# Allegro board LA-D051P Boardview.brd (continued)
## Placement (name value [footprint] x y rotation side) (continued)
RE353  10K_0402_5%  [R_0402]  142.55 22.71 90 top
RE354  100K_0402_5%  [R_0402]  147.82 21.82 90 top
RE355  10K_0402_5%  [R_0402]  131.63 22.2 90 top
RE356  100K_0402_5%  [R_0402]  154.36 12.55 90 top
RE357  1K_0402_5%  [R_0402]  128.15 13.64 180 top
RE358  100K_0402_5%  [R_0402]  150.16 5.77 0 top
RE359  10K_0402_5%  [R_0402]  123.62 9.26 0 top
RE360  100K_0402_5%  [R_0402]  128.09 8.44 180 top
RE361  100K_0402_5%  [R_0402]  128.15 17.52 180 top
RE362  0_0402_5%  [R0402_0OHM]  123.62 8.37 0 top
RE363  10K_0402_5%  [R_0402]  140.9 24.96 270 top
RE364  43_0402_1%  [R_0402]  126.31 4.5 180 top
RE365  0_0402_5%  [R_0402]  124.53 4.5 180 top
RE366  10_0402_5%  [R_0402]  140.01 24.96 270 top
RE367  0_0402_5%  [R_0402]  124.53 7.29 180 top
RE368  0_0402_5%  [R0402_0OHM]  124.53 5.39 180 top
RE369  1K_0402_5%  [R_0402]  155.81 3.67 0 top
RE370  100K_0402_5%  [R_0402]  148.63 3.74 0 top
RE371  100K_0402_5%  [R_0402]  155.81 2.72 0 top
RE372  15_0402_1%  [R_0402]  151.01 21.9 180 top
RE373  15_0402_1%  [R_0402]  151.01 19.04 180 top
RE374  15_0402_1%  [R_0402]  151.01 19.99 180 top
RE375  0_0402_5%  [R0402_0OHM]  152.39 17.33 0 top
RE376  100K_0402_5%  [R_0402]  153.42 5.71 180 top
RE377  0_0402_5%  [R0402_0OHM]  150.09 18.09 0 top
RE378  10K_0402_5%  [R_0402]  152.51 6.6 0 top
RE379  10K_0402_5%  [R_0402]  154.3 9.06 90 top
RE380  10K_0402_1%  [R_0402]  153.3 16.44 180 top
RE381  0_0402_5%  [R0402_0OHM]  138.23 21.82 90 top
RE382  0_0402_5%  [R0402_0OHM]  142.98 1.58 0 top
RE383  10K_0402_1%  [R_0402]  151 16.23 90 top
RE384  100K_0402_5%  [R_0402]  123.62 10.28 0 top
RE385  0_0603_5%  [R0603_0OHM]  114.55 1.77 90 top
RE386  300_0402_5%  [R_0402]  124.53 2.59 180 top
RE387  100K_0402_5%  [R_0402]  123.62 11.17 0 top
RE388  100K_0402_5%  [R_0402]  124.53 12.06 180 top
RE389  300_0402_5%  [R_0402]  121.48 2.59 180 top
RE390  49.9_0402_1%  [R_0402]  122.24 3.61 180 top
RE391  10K_0402_5%  [R_0402]  122.24 8.18 180 top
RE392  10K_0402_5%  [R_0402]  122.24 10.09 180 top
RE393  10K_0402_5%  [R_0402]  122.24 11.04 180 top
RE394  100K_0402_5%  [R_0402]  122.24 9.14 180 top
RE395  0_0402_5%  [R_0402]  122.24 4.5 180 top
RE396  0_0402_5%  [R_0402]  122.24 5.45 180 top
RE397  0_0402_5%  [R_0402]  122.24 6.34 180 top
RE398  0_0402_5%  [R_0402]  122.24 7.29 180 top
RE399  0_0402_5%  [R_0402]  26.4 63.05 0 top
RE400  0_0402_5%  [R0402_0OHM]  23.12 69.52 180 top
RE401  1K_0402_5%  [R_0402]  92.44 51.87 0 top
RE402  100_0402_1%  [R_0402]  21.33 67.73 90 top
RE403  0_0402_5%  [R_0402]  113.42 2.53 180 top
RI1  -  [DMN66D0LDW-7_SOT363-6]  14.9 43.11 0 top
RI3  0_0402_5%  [R_0402]  16.06 82.05 270 top
RI4  0_0402_5%  [R_0402]  15.04 82.05 270 top
RI5  0_0402_5%  [R_0402]  18.03 79.95 270 top
RI6  0_0402_5%  [R_0402]  16.95 79.95 270 top
RI19  4.7K_0402_5%  [R_0402]  23.44 86.22 180 bottom
RI20  4.7K_0402_5%  [R_0402]  20.75 86.22 0 bottom
RI21  4.7K_0402_5%  [R_0402]  18.41 86.94 270 top
RI22  4.7K_0402_5%  [R_0402]  22.6 78.78 90 bottom
RI23  4.7K_0402_5%  [R_0402]  20.82 78.78 90 bottom
RI26  4.7K_0402_5%  [R_0402]  21.71 78.78 90 bottom
RI31  4.7K_0402_5%  [R_0402]  21.65 84.41 90 bottom
RI32  4.7K_0402_5%  [R_0402]  20.76 82.43 270 bottom
RI35  4.7K_0402_5%  [R_0402]  21.65 82.43 270 bottom
RI36  4.7K_0402_5%  [R_0402]  20.76 84.41 90 bottom
RI40  4.7K_0402_5%  [R_0402]  22.54 82.43 270 bottom
RI42  4.7K_0402_5%  [R_0402]  24.31 86.24 270 bottom
RI44  4.7K_0402_5%  [R_0402]  22.09 78.66 90 top
RI46  4.7K_0402_5%  [R_0402]  23.42 84.41 90 bottom
RI48  4.7K_0402_5%  [R_0402]  22.98 78.66 90 top
RI49  0_0402_5%  [R_0402]  23.87 78.66 90 top
RI50  0_0402_5%  [R_0402]  16.62 85.27 0 top
RI52  3.3K_0402_5%  [R_0402]  16.62 86.16 0 top
RI53  3.3K_0402_5%  [R_0402]  24.76 78.66 90 top
RI54  10K_0402_5%  [R_0402]  17.84 61.26 90 top
RI55  10K_0402_5%  [R_0402]  16.69 62.17 270 top
RI56  4.99K_0402_1%  [R_0402]  25.25 81.46 0 top
RI57  0_0402_5%  [R_0402]  18.98 79.57 270 top
RI87  4.7K_0402_5%  [R_0402]  22.54 84.41 90 bottom
RI88  10K_0402_5%  [R_0402]  19.61 61.26 90 top
RI89  10K_0402_5%  [R_0402]  11.8 50.84 90 bottom
RI90  100K_0402_5%  [R_0402]  18.73 62.17 270 top
RI91  100K_0402_5%  [R_0402]  17.33 39.22 90 top
RI93  100K_0402_5%  [R_0402]  14.78 38.41 0 top
RI94  100K_0402_5%  [R_0402]  14.9 45.97 0 top
RI95  0_0402_5%  [R_0402-NPM]  195.18 58.67 0 bottom
RI96  0_0402_5%  [R_0402-NPM]  195.18 59.55 0 bottom
RI97  0_0402_5%  [R_0402]  195.83 69.85 270 bottom
RI98  0_0402_5%  [R_0402]  194.94 69.85 270 bottom
RI99  0_0402_5%  [R_0402]  194.05 69.85 270 bottom
RI100  0_0402_5%  [R_0402]  193.16 69.85 270 bottom
RI101  0_0402_5%  [R_0402-NPM]  189.97 43.36 0 bottom
RI102  0_0402_5%  [R_0402-NPM]  189.97 44.25 0 bottom
RI103  0_0402_5%  [R_0402]  192.64 48.57 0 bottom
RI104  0_0402_5%  [R_0402]  192.64 47.68 0 bottom
RI105  0_0402_5%  [R_0402]  192.64 45.9 0 bottom
RI106  0_0402_5%  [R_0402]  192.64 46.79 0 bottom
RI107  0_0402_5%  [R_0402-NPM]  30.04 57.01 180 bottom
RI108  0_0402_5%  [R_0402-NPM]  30.04 57.9 180 bottom
RI109  0_0402_5%  [R_0402-NPM]  30.04 54.03 180 bottom
RI110  0_0402_5%  [R_0402-NPM]  30.04 54.92 180 bottom
RI111  0_0805_5%  [R0805_0OHM]  196.08 45.55 270 top
RL1  0_0603_5%  [MURAT_BLM18AG601SN1D_L0603_2P]  171.1 109.4 0 bottom
RL6  0_0603_5%  [R0603_0OHM]  170.94 103.43 90 bottom
RL19  75_0603_5%  [R_0603]  189.92 104.58 180 top
RL20  75_0603_5%  [R_0603]  190.01 107.78 180 top
RL27  100K_0402_5%  [R_0402]  185.48 97.2 90 bottom
RL31  2.49K_0402_1%  [R_0402]  176.59 104.88 90 top
RL33  1K_0402_5%  [R_0402]  173.11 100.89 180 top
RL35  15K_0402_5%  [R_0402]  173.11 101.78 180 top
RL39  10K_0402_5%  [R_0402]  173.46 105.8 0 top
RL40  10K_0402_5%  [R_0402]  187.51 93.58 90 bottom
RM5  0_0402_1%  [R0402_0OHM]  184.71 65.79 270 top
RM6  0_0402_1%  [R0402_0OHM]  185.6 65.79 270 top
RM7  0_0603_5%  [R0603_0OHM]  192.72 68.51 270 top
RM8  10K_0402_5%  [R_0402]  187.46 65.71 180 top
RM9  100K_0402_5%  [R_0402]  180.78 65.79 270 top
RM10  0_0603_5%  [R0603_0OHM]  191.45 68.51 270 top
RM11  0_0402_5%  [R_0402]  193.87 65.08 180 top
RM12  0_0402_5%  [R_0402]  182.56 65.79 270 top
RM13  0_0402_1%  [R0402_0OHM]  181.67 65.79 270 top
RM14  0_0402_5%  [R_0402]  184.56 55.43 180 bottom
RP58  470_8P4R_5%  [RP_0804_8P4R]  195.51 87.95 180 top
RP59  470_8P4R_5%  [RP_0804_8P4R]  195.96 80.84 180 top
RPC1  2.2K_0804_8P4R_5%  [RP_0804_8P4R]  164.2 88.52 0 bottom
RPC5  15_0804_8P4R_5%  [RP_0804_8P4R]  180.79 23.86 90 top
RPC7  1K_0804_8P4R_5%  [RP_0804_8P4R]  156.07 96.33 0 bottom
RPC9  33_0804_8P4R_5%  [RP_0804_8P4R]  142.12 70.16 90 top
RPC10  10K_0804_8P4R_5%  [RP_0804_8P4R]  154.98 73.91 270 top
RPC11  10K_0804_8P4R_5%  [RP_0804_8P4R]  158.54 64.13 270 top
RPC14  10K_0804_8P4R_5%  [RP_0804_8P4R]  151.43 106.54 90 bottom
RPC18  1K_0804_8P4R_5%  [RP_0804_8P4R]  151.69 93.64 0 top
RPE1  10K_8P4R_5%  [RP_0804_8P4R]  151.71 9 90 top
RPE2  10K_8P4R_5%  [RP_0804_8P4R]  126.61 7.09 0 top
RPE3  100K_8P4R_5%  [RP_0804_8P4R]  153.21 13.77 270 top
RPE4  100K_8P4R_5%  [RP_0804_8P4R]  146.67 23.36 270 top
RPE5  100K_8P4R_5%  [RP_0804_8P4R]  126.61 16.24 0 top
RPE6  100K_8P4R_5%  [RP_0804_8P4R]  126.61 11.22 0 top
RPV3  2.2K_0804_8P4R_5%  [RP_0804_8P4R]  84.89 87.19 0 bottom
RPV5  10K_0804_8P4R_5%  [RP_0804_8P4R]  80.52 79.51 0 top
RPV6  10K_0804_8P4R_5%  [RP_0804_8P4R]  79.89 69.18 0 bottom
RPV7  10K_0804_8P4R_5%  [RP_0804_8P4R]  85.1 78.01 180 top
RPV8  100_0804_8P4R_5%  [RP_0804_8P4R]  40.76 96.4 180 top
RPV9  100_0804_8P4R_5%  [RP_0804_8P4R]  45.85 93.33 90 top
RPV10  100_0804_8P4R_5%  [RP_0804_8P4R]  36.7 96.4 180 top
RPV11  100_0804_8P4R_5%  [RP_0804_8P4R]  42.1 93.41 180 top
RPV12  100_0804_8P4R_5%  [RP_0804_8P4R]  45.9 91.55 0 top
RPV13  100_0804_8P4R_5%  [RP_0804_8P4R]  43.63 99.11 90 top
RPV14  100_0804_8P4R_5%  [RP_0804_8P4R]  42.86 90.36 180 top
RPV15  100_0804_8P4R_5%  [RP_0804_8P4R]  40.84 100.25 90 top
RPV16  100_0804_8P4R_5%  [RP_0804_8P4R]  44.77 96.25 90 top
RPV17  100_0804_8P4R_5%  [RP_0804_8P4R]  37.72 100.25 90 top
RPV18  100_0804_8P4R_5%  [RP_0804_8P4R]  38.46 93.15 225 top
RS8  0_0402_1%  [R0402_0OHM]  181.21 14.09 0 bottom
RS18  0_0402_5%  [R_0402]  183.58 8.26 270 top
RS19  0_0402_5%  [R_0402]  185.1 16.39 270 top
RS20  0_0402_5%  [R_0402]  185.35 7.34 90 top
RS21  0_0402_5%  [R_0402]  183.32 15.47 90 top
RS22  0_0402_5%  [R_0402]  184.47 7.34 90 top
RS23  0_0402_5%  [R_0402]  187.13 8.26 270 top
RS24  2K_0402_5%  [R_0402]  182.43 15.47 90 top
RS25  0_0402_5%  [R_0402]  180.51 16.39 270 top
RS26  0_0402_5%  [R_0402]  188.91 7.34 90 top
RS27  0_0402_5%  [R_0402]  181.46 16.39 270 top
RS28  0_0402_5%  [R_0402]  184.21 16.39 270 top
RS29  0_0402_5%  [R_0402]  182.71 7.33 90 top
RS30  0_0402_5%  [R_0402]  186.24 7.34 90 top
RS31  5.1K_0402_1%  [R_0402]  188.02 8.26 270 top
RS33  4.7K_0402_5%  [R_0402]  186.87 16.39 270 top
RS34  4.7K_0402_5%  [R_0402]  181.79 8.26 270 top
RS35  4.7K_0402_5%  [R_0402]  185.98 15.47 90 top
RS36  4.7K_0402_5%  [R_0402]  180.9 8.26 270 top
RS37  0_0402_5%  [R_0402]  178.22 9.15 180 top
RS38  0_0402_5%  [R_0402]  178.22 7.34 90 top
RV4  200_0402_1%  [R_0402]  57.27 66.12 270 top
RV5  0_0402_5%  [R0402_0OHM]  75.55 68.13 0 top
RV6  2.49K_0402_1%  [R_0402]  55.46 65.15 0 top
RV9  0_0402_5%  [R_0402]  80.41 66.76 180 bottom
RV12  0_0402_5%  [R0402_0OHM]  63.76 66.49 90 top
RV20  10K_0402_1%  [R_0402]  76.96 89.04 0 bottom
RV21  10K_0402_1%  [R_0402]  66.99 86.62 270 top
RV23  10K_0402_1%  [R_0402]  76.4 89.72 180 top
RV24  1K_0402_1%  [R_0402]  75.67 91.81 0 bottom
RV40  0_0402_5%  [R0402_0OHM]  78.25 79.01 180 top
RV41  40.2_0402_1%  [R_0402]  58.7 83.38 90 top
RV42  42.2_0402_1%  [R_0402]  57.79 85.08 180 top
RV43  51.1_0402_1%  [R_0402]  54.79 83.42 90 top
RV44  40.2K_0402_1%  [R_0402]  79.69 82.57 0 top
RV45  4.99K_0402_1%  [R_0402]  82.82 82.76 180 bottom
RV46  4.99K_0402_1%  [R_0402]  82.82 87.33 180 bottom
RV47  49.9K_0402_1%  [R_0402]  82.82 85.11 180 bottom
RV48  45.3K_0402_1%  [R_0402]  79.69 83.9 0 bottom
RV49  4.99K_0402_1%  [R_0402]  79.75 82.76 0 bottom
RV50  15K_0402_1%  [R_0402]  79.75 87.33 0 bottom
RV51  4.99K_0402_1%  [R_0402]  82.81 84.19 180 bottom
RV52  4.99K_0402_1%  [R_0402]  79.75 85.11 0 bottom
RV58  0_0402_5%  [R0402_0OHM]  69.35 80.93 270 top
RV61  10K_0402_1%  [R_0402]  82.82 86.12 180 bottom
RV62  45.3K_0402_1%  [R_0402]  79.75 86.12 0 bottom
RV63  4.99K_0402_1%  [R_0402]  69.58 85.78 0 top
RV64  4.99K_0402_1%  [R_0402]  71.43 90.12 0 bottom
RV65  24.9K_0402_1%  [R_0402]  67.87 84.69 90 top
RV66  10K_0402_5%  [R_0402]  79.5 65.8 0 bottom
RV67  10K_0402_5%  [R_0402]  79.88 71.9 0 bottom
RV68  10K_0402_5%  [R_0402]  73.98 68.13 180 top
RV69  100K_0402_5%  [R_0402]  79.69 83.52 0 top
RV74  0_0402_5%  [R_0402]  79.88 73.8 0 bottom
RV75  0_0402_5%  [R_0402]  81.05 77.68 180 bottom
RV80  4.99K_0402_1%  [R_0402]  70.49 86.73 180 top
RV81  4.99K_0402_1%  [R_0402]  72.35 89.17 180 bottom
RV82  60.4_0402_1%  [R_0402]  58.68 81.85 270 top
RV83  60.4_0402_1%  [R_0402]  58.72 77.75 0 top
RV84  4.99K_0402_1%  [R_0402]  70.49 87.68 180 top
RV88  10K_0402_5%  [R_0402]  82.11 75.95 90 top
RV94  1.33K_0402_1%  [R_0402]  31.95 79.18 180 top
RV95  1.33K_0402_1%  [R_0402]  31.03 68.76 0 top
RV96  1.33K_0402_1%  [R_0402]  31.95 70.03 180 top
RV97  243_0402_1%  [R_0402]  37.95 77.27 0 top
RV98  243_0402_1%  [R_0402]  38.86 61.89 90 top
RV99  243_0402_1%  [R_0402]  39.22 74.86 0 bottom
RV100  1.33K_0402_1%  [R_0402]  31.95 80.45 180 top
RV101  243_0402_1%  [R_0402]  38.54 89.4 0 bottom
RV107  1.33K_0402_1%  [R_0402]  75.49 103.55 90 bottom
RV108  1.33K_0402_1%  [R_0402]  75.49 106.37 270 bottom
RV111  243_0402_1%  [R_0402]  63.06 100.4 270 top
RV112  243_0402_1%  [R_0402]  60.89 100.4 270 bottom
RV113  1.33K_0402_1%  [R_0402]  48.77 101.34 180 bottom
RV114  243_0402_1%  [R_0402]  76.4 101.72 180 bottom
RV115  1.33K_0402_1%  [R_0402]  47.86 102.42 0 bottom
RV116  243_0402_1%  [R_0402]  47.86 101.34 0 top
RV129  47K_0402_5%  [R_0402]  87.69 66.93 270 top
RV201  0_0402_5%  [R_0402]  82.11 75.02 270 top
RV202  0_0402_5%  [R_0402]  80.26 76.85 0 top
RV203  2.2K_0402_5%  [R_0402]  79.75 88.79 0 bottom
RV204  2.2K_0402_5%  [R_0402]  79.75 89.69 0 bottom
RV205  2.2K_0402_5%  [R_0402]  76.96 89.93 0 bottom
RV206  2.2K_0402_5%  [R_0402]  76.96 90.82 0 bottom
RV207  0_0603_5%  [R0603_0OHM]  92.7 57.92 90 top
RV208  0_0402_5%  [R_0402]  83.88 72.31 180 top
RV209  0_0805_5%  [R0805_0OHM]  93.49 64.63 180 top
RV210  0_0402_5%  [R0402_0OHM]  94.18 63.24 180 top
RV211  0_0402_5%  [R0402_0OHM]  83.88 71.4 180 top
RV212  100K_0402_5%  [R_0402]  87.67 67.81 0 top
RV2437  10K_0402_5%  [R_0402]  40.71 77.27 180 top
RV2438  10K_0402_5%  [R_0402]  61.4 100.4 270 top
RV2439  10K_0402_5%  [R_0402]  41.57 77.27 0 top
RV2440  10K_0402_5%  [R_0402]  63.3 95.67 90 top
RV2447  10K_0402_5%  [R_0402]  36.68 98.99 0 top
RV2706  162_0402_1%  [R_0402]  63.32 96.78 270 bottom
RV2717  162_0402_1%  [R_0402]  43.43 74.86 0 bottom
RV2718  470_0603_5%  [R_0603]  83.5 66.48 90 top
RV2719  100K_0402_5%  [R_0402]  85.15 70.93 270 top
RV2720  10K_0402_5%  [R_0402]  95.31 68.88 90 top
RV2721  470_0603_5%  [R_0603]  87.57 75.95 45 top
RX4  0_0805_5%  [R_0805]  8.65 74.98 180 top
RX9  100K_0402_5%  [R_0402]  4.17 80.06 0 top
RX10  10K_0402_5%  [R_0402]  24.46 74.88 270 top
RX12  10K_0402_5%  [R_0402]  197.21 74.22 0 top
RX13  100K_0402_5%  [R_0402]  199.76 84.08 270 top
RX14  100K_0402_5%  [R_0402]  197.21 75.11 0 top
RX15  150K_0402_5%  [R_0402]  197.21 73.33 0 top
RX16  2.2K_0402_5%  [R_0402]  197.49 75.81 180 bottom
RX17  2.2K_0402_5%  [R_0402]  194.8 75.81 0 bottom
RX21  0_0402_5%  [R_0402-NPM]  5.85 84.64 180 top
RX22  0_0402_5%  [R_0402-NPM]  5.85 85.59 180 top
RX23  0_0402_1%  [R0402_0OHM]  11.18 90.61 180 top
RX24  0_0402_5%  [R_0402]  5.21 90.48 180 top
RX25  0_0402_1%  [R0402_0OHM]  11.18 91.56 180 top
RX26  100K_0402_5%  [R_0402]  4.17 81.08 0 top
RX27  0_0603_1%  [R0603_0OHM]  6.47 83.49 180 top
RX28  0_0603_5%  [R_0603]  9.65 99.11 0 top
RX29  0_0603_5%  [R_0603]  11.23 101.72 270 top
RX30  0_0603_5%  [R_0603]  9.71 101.72 270 top
RX31  100_0402_5%  [R_0402]  7.44 80.06 180 top
RX32  0_0402_1%  [R0402_0OHM]  12.12 83.06 270 top
RX33  0_0402_5%  [R_0402]  12.12 80.31 90 top
RX34  20K_0402_5%  [R_0402]  198.13 72.44 180 top
RX35  5.6_0402_1%  [R_0402]  197.59 82.92 0 bottom
RX36  150_0402_1%  [R_0402]  200.02 82.91 90 bottom
RX37  5.6_0402_1%  [R_0402]  197.59 83.81 0 bottom
RX38  5.6_0402_1%  [R_0402]  197.59 79.37 0 bottom
RX39  150_0402_1%  [R_0402]  200.02 79.35 90 bottom
RX40  5.6_0402_1%  [R_0402]  197.59 80.26 0 bottom
RX41  5.6_0402_1%  [R_0402]  197.66 86.48 0 bottom
RX42  150_0402_1%  [R_0402]  200.08 86.47 90 bottom
RX43  5.6_0402_1%  [R_0402]  197.66 87.37 0 bottom
RX44  5.6_0402_1%  [R_0402]  197.47 89.84 0 bottom
RX45  150_0402_1%  [R_0402]  199.89 89.83 90 bottom
RX46  5.6_0402_1%  [R_0402]  197.47 90.73 0 bottom
RX47  100K_0402_5%  [R_0402]  5.21 89.29 180 top
RX48  100K_0402_5%  [R_0402]  14.69 88.04 90 top
RX49  0_0402_5%  [R_0402]  10.27 89.65 0 top
RZ75  0_0402_5%  [R_0402]  173.17 49.65 180 top
SW1  SMT1-05-A_4P  [SW_SMT1-05-A_4P]  172.28 113.17 90 top
T10  PAD~D  [TPC12]  123.69 106.1 180 bottom
T11  PAD~D  [TPC12]  122.36 106.29 180 bottom
T14  PAD~D  [TPC12]  119.25 74.41 0 top
T15  PAD~D  [TPC12]  117.66 73.52 180 bottom
T16  PAD~D  [TPC12]  122.93 107.62 180 bottom
T17  PAD~D  [TPC12]  121.09 85.59 0 top
T18  PAD~D  [TPC12]  122.04 84.38 0 top
T19  PAD~D  [TPC12]  124.39 104.77 180 bottom
T22  PAD~D  [TPC12]  122.87 85.65 0 top
T23  PAD~D  [TPC12]  127.5 85.08 0 top
T87  PAD~D  [TPC12]  144.77 77.97 180 bottom
T88  PAD~D  [TPC12]  142.36 77.97 180 bottom
T89  PAD~D  [TPC12]  128.45 99.24 0 top
T90  PAD~D  [TPC12]  128.39 99.75 0 top
T91  PAD~D  [TPC12]  145.79 83.11 0 top
T93  PAD~D  [TPC12]  143.06 85.59 0 top
T121  PAD~D  [TPC12]  133.72 87.3 0 top
T123  PAD~D  [TPC12]  133.91 97.65 0 top
T124  PAD~D  [TPC12]  137.56 85.64 0 top
T125  PAD~D  [TPC12]  138.49 84.32 0 top
T130  PAD~D  [TPC12]  147.38 85.91 0 top
T131  PAD~D  [TPC12]  144.27 84.7 0 top
T132  PAD~D  [TPC12]  118.04 90.92 0 top
T133  PAD~D  [TPC12]  115.18 89.65 0 top
T137  PAD~D  [TPC12]  116.96 86.67 0 top
T139  PAD~D  [TPC12]  117.02 89.08 0 top
T155  PAD~D  [TPC12]  118.61 88.57 0 top
T156  PAD~D  [TPC12]  106.17 76.32 180 bottom
T157  PAD~D  [TPC12]  104.7 76.25 180 bottom
T158  PAD~D  [TPC12]  144.07 88 0 top
T159  PAD~D  [TPC12]  146.23 87.3 0 top
T162  PAD~D  [TPC12]  148.46 84.89 0 top
T163  PAD~D  [TPC12]  149.73 84.07 0 top
T199  PAD~D  [TPC12]  163.12 76.13 180 bottom
T213  PAD~D  [TPC12]  107.63 77.91 180 bottom
T214  PAD~D  [TPC12]  161.79 76.13 180 bottom
T215  PAD~D  [TPC12]  106.23 77.78 180 bottom
T216  PAD~D  [TPC12]  161.28 77.33 180 bottom
T219  PAD~D  [TPC12]  118.67 86.86 0 top
T221  PAD~D  [TPC12]  106.99 79.43 180 bottom
T223  PAD~D  [TPC12]  108.39 79.18 180 bottom
T225  PAD~D  [TPC12]  118.99 83.37 0 top
T230  PAD~D  [TPC12]  119.37 85.46 0 top
T231  PAD~D  [TPC12]  72.38 65.84 180 top
T232  PAD~D  [TPC12]  71.49 67.36 180 top
T242  PAD~D  [TPC12]  72.38 64 0 top
T243  PAD~D  [TPC12]  71.11 63.55 0 top
T2401  PAD~D  [TPC12]  57.67 83.71 180 top
T4928  PAD~D  [TPC12]  183.51 65.46 180 top
T4931  PAD  [TPC12]  123.37 6.34 0 top
T4932  PAD~D  [TPC12]  108.64 105.85 180 bottom
T4933  PAD~D  [TPC12]  107.56 104.83 180 bottom
T4934  PAD~D  [TPC12]  107.37 106.1 180 bottom
T4935  PAD~D  [TPC12]  108.77 107.37 180 bottom
T4936  PAD~D  [TPC12]  116.52 99.31 0 top
T4937  PAD~D  [TPC12]  115.88 101.08 0 top
T4938  PAD~D  [TPC12]  105.21 100.64 180 bottom
T4939  PAD~D  [TPC12]  107.37 98.86 180 bottom
T4940  PAD~D  [TPC12]  107.18 100.44 180 bottom
T4941  PAD~D  [TPC12]  104.83 99.31 180 bottom
T4942  PAD~D  [TPC12]  109.15 99.31 180 bottom
T4943  PAD~D  [TPC12]  108.51 100.45 180 bottom
T4944  PAD~D  [TPC12]  113.15 100.89 0 top
T4945  PAD~D  [TPC12]  108.51 101.85 180 bottom
T4946  PAD~D  [TPC12]  108.51 103.18 180 bottom
T4947  PAD~D  [TPC12]  108.96 97.91 180 bottom
T4948  PAD~D  [TPC12]  106.23 99.5 180 bottom
T4949  PAD~D  [TPC12]  105.15 97.97 180 bottom
T4950  PAD~D  [TPC12]  114.42 99.31 0 top
T4951  PAD~D  [TPC12]  114.55 100.64 0 top
T4956  PAD~D  [TPC12]  118.48 107.62 180 bottom
T4962  PAD~D  [TPC12]  157.98 65.59 0 top
T4963  PAD~D  [TPC12]  118.23 105.27 180 bottom
T4964  PAD~D  [TPC12]  120.39 105.91 180 bottom
TL2  350UH_LF-H1201P-2  [LANKO_LF-H1201P-2_16P]  180.59 102.04 90 bottom
U2301  -  [TPS22966DPUR_SON14_2X3]  169.42 13.13 0 top
U2407  F75303M_MSOP10  [EMC1403-2-AIZL-TR_MSOP10]  155.97 8.26 0 top
U2409  TPS22967DSGR_SON8_2X2  [AOZ1336_DFN8_2X2]  17.91 63.79 0 top
UA1  -  [ALC3234-CG_MQFN48_6X6]  198.73 16.44 180 bottom
UC1  SKL-U_BGA1356  [SKL-U_BGA_1356P-T]  152.1 102.61 0 bottom
UC2  W25Q128FVSIQ_SO8  [W25R128FVSIQ_SO8]  180.33 25.9 0 bottom
UC3  -  [TC7SH08FUF_SSOP5]  163.24 61.93 0 top
UC4  -  [TPS22961DNYR_WSON8]  185.77 76.37 0 top
UC5  EM5209VF_DFN14_2X3  [TPS22966DPUR_SON14_2X3]  176.96 75.67 0 top
UC6  -  [TPS22961DNYR_WSON8]  167.97 43.59 90 top
UC7  -  [74AUP1G07GW_TSSOP5]  157.52 57.96 0 top
UC8  -  [SY6288C20AAC_SOT23-5]  175.43 93.79 0 top
UC11  -  [TC7SH08FUF_SSOP5]  155.02 67.82 270 top
UC12  -  [74AUP1G07GW_TSSOP5]  107.3 109.58 90 bottom
UC13  -  [74AUP1G07GW_TSSOP5]  128.21 22.34 90 top
UC15  TC7SH08FU_SSOP5~D  [TC7SH08FU_SSOP5]  172.27 47.28 90 top
UE3  NCT3942S SOP 8P  [G993P1UF_SOP8]  6.79 69.57 180 top
UE5  MEC1404-NU-D0_VTQFP128_14X14  [MEC1404-NU-TR_VTQFP128_14X14]  146.63 5.35 180 top
UE6  -  [SN74LVC1G06DCKR_SC70-5]  123.17 13.28 0 top
UI5  -  [SY6288D20AAC_SOT23-5]  194.04 46.86 90 top
UI6  -  [SY6288D20AAC_SOT23-5]  194 43.24 90 top
UI7  -  [SY6288D20AAC_SOT23-5]  28.58 44.82 90 bottom
UI8  PS8713BTQFN24GTR2-A0_TQFN24_4X4  [SN65LVPE502CPRGER_VQFN24_4X4]  20.52 81.46 0 top
UL1  RTL8106E-CG QFN 32P E-LAN CTRL  [RTL8106EUS-CG_QFN32_4X4]  177.62 104.96 270 bottom
UL3  -  [SY6288C20AAC_SOT23-5]  189.47 95.63 180 bottom
US2  -  [PS8520BTQFN20GTR2_TQFN20_4X4]  187.12 10.87 90 top
UV1  N16S-GT-S-A2_BGA595  [N16S-GT-S-A2_BGA_595P]  75.7 85.4 180 bottom
UV4  H5TC4G63AFR-11C_FBGA96  [MT41K256M16HA-125M-E_FBGA_96P]  51.67 93.18 0 bottom
UV5  H5TC4G63AFR-11C_FBGA96  [MT41K256M16HA-125M-E_FBGA_96P]  72.55 93.18 180 top
UV6  H5TC4G63AFR-11C_FBGA96  [MT41K256M16HA-125M-E_FBGA_96P]  46.52 72.03 270 top
UV7  H5TC4G63AFR-11C_FBGA96  [MT41K256M16HA-125M-E_FBGA_96P]  46.52 86.5 270 top
UV8  H5TC4G63AFR-11C_FBGA96  [MT41K256M16HA-125M-E_FBGA_96P]  66.15 93.18 0 bottom
UV9  H5TC4G63AFR-11C_FBGA96  [MT41K256M16HA-125M-E_FBGA_96P]  58.07 93.18 180 top
UV10  EM5209VF_DFN14_2X3  [TPS22966DPUR_SON14_2X3]  91.58 60.71 90 top
UV12  -  [TC7SH08FUF_SSOP5]  83.92 83.28 270 top
UV13  -  [TC7SH08FUF_SSOP5]  82.48 66.54 0 bottom
UV14  H5TC4G63AFR-11C_FBGA96  [MT41K256M16HA-125M-E_FBGA_96P]  46.52 65.62 90 bottom
UV15  H5TC4G63AFR-11C_FBGA96  [MT41K256M16HA-125M-E_FBGA_96P]  46.52 80.1 90 bottom
UV23  MC74VHC1G32DFT2G SC70-5  [NC7ST32P5X_SC70-5]  84.67 76.41 180 top
UX4  -  [SY6288C20AAC_SOT23-5]  21.27 74.08 0 top
Y1  32.768KHZ_9PF_CM315D32768DZCT  [Y_Q13FC135000040_2P]  149.49 2.15 0 top
YC1  24MHZ_12PF_7V24000020  [Y_7V24000020_4P]  131.78 109.78 0 bottom
YC2  32.768KHZ_12.5PF_9H03280012  [Y_9H03200031_2P]  158.87 82.05 90 bottom
YL2  25MHZ_10PF_7V25000014  [Y_FSX3M-25PM20FDO_4P]  176.8 108.6 180 bottom
YV1  27MHZ_10PF_7V27000023  [Y_7V27000050_4P]  78.12 94.07 180 bottom

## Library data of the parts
C94 C2498 C2500 C2502 C2504 C2505 C4311-C4314 C4321 C4322 C5216 C5217 C5220-C5225 C5230 C5232 C5233 CA21 CA26 CA32 CA38-CA40 CA54 CA56 CA58 CA60 CA65 CA69 CC12 CC13 CC15-CC17 CC23 CC24 CC36 CC43 CC45-CC48 CC50 CC52 CC55 CC58 CC59 CC61 CC63 CC64 CC67 CC71-CC77 CC84-CC91 CC93-CC104 CC117 CC122 CC135 CC136 CC141 CC142 CE26 CE58 CE61 CE63-CE92 CI2 CI5 CI9 CI15 CI16 CI19-CI24 CI26 CI45-CI47 CL3 CL5-CL9 CL12 CL16 CL30 CL31 CL36 CL37 CL39 CL41 CM5 CM7-CM10 CS5 CS6 CS27 CS30-CS37 CS42 CV11-CV18 CV22 CV29 CV31 CV34 CV36 CV37 CV41 CV42 CV47 CV49 CV53 CV55-CV59 CV63-CV65 CV67 CV117 CV162 CV166-CV168 CV200 CV204-CV207 CV236 CV237 CV241 CV242 CV248 CV249 CV251 CV252 CV254 CV255 CV259 CV260 CV262 CV264 CV268 CV269 CV275 CV276 CV278 CV279 CV284 CV285 CV287-CV293 CV295-CV302 CX1 CX2 CX4 CX9 CX11-CX19 CX21 CX50 PC2 PC7 PC8 PC14 PC16 PC103 PC116 PC127 PC128 PC202 PC210 PC214 PC405 PC503 PC505 PC506 PC601 PC602 PC605 PC613 PC614 PC616-PC621 PC624-PC633 PC636 PC637 PC639-PC647 PC649-PC654 PC659-PC661 PC666 PC667 PC677 PC679 PC680 PC685 PC686 PC688 PC747-PC749 PC751-PC753 PC765 PC768 PC769 PC777 PC779 PC801 PC802 PC804 PC805 PC813 PC814 PC819 PC820 PC835 PC841 PC844 PC847 PC858-PC861 = C_0402
C2305 C2306 C2308 C2309 C2316 C2318 C2322-C2324 C5231 CA55 CA57 CA59 CA61-CA64 CA67 CA68 CA71 CA74 CC37-CC39 CC41 CC42 CC51 CC81 CC82 CC111-CC116 CC118 CC119 CC123-CC130 CE56 CE57 CE62 CI40 CI43 CL4 CL13 CL14 CL17 CM4 CM6 CV9 CV10 CV21 CV24 CV25 CV28 CV30 CV32 CV35 CV38 CV40 CV44 CV45 CV48 CV51 CV54 CV163 CV169 CV170 CV203 CV238 CV243-CV245 CV256 CV261 CV265 CV270-CV272 CV280 CV281 CX5 CX6 CX22 PC112 PC119 PC125 PC126 PC215-PC220 PC312 PC313 PC501 PC502 PC504 PC603 PC604 PC611 PC622 PC655 PC662 PC671 PC678 PC750 PC757 PC767 PC803 PC806-PC808 PC821-PC830 PC842 PC843 PC845 PC846 PC848 PC850 PC1001-PC1029 PC1057-PC1061 PC1064-PC1066 PC1069-PC1082 PC1129-PC1146 PC1154-PC1156 PC1158 PC1159 PC1161-PC1163 PC1173-PC1184 PC1221-PC1224 = C_0603
C2307 CI18 CI44 CS7 CX3 CX7 CX8 CX49 CX51 PC104 PC106-PC108 PC117 PC118 PC120-PC124 PC206 PC311 PC608 PC612 PC656-PC658 PC672 PC673 PC760-PC764 PC766 PC775 PC776 PC840 PC849 PC2118-PC2121 = C_0805
CA22 CA24 CA25 CA29-CA31 CA33 CA51 = C_0402: room: CODEC
CA23 CA53 CV61 = C_0603: room: CODEC
CC8 CC31 CC32 = C_0201: room: CPU
CC9 CC10 = C_0402: room: SPI
CC11 CC18-CC22 CC25-CC28 CC33-CC35 PC207 = C_0402: room: CPU
CC14 CC29 CC30 CC44 CC49 CC56 CC57 CC68 CC78-CC80 CC83 CC92 CV19 CV20 CV39 CV43 CV46 CV50 CV69 CV76 CV79 CV164 CV165 CV198 CV199 CV201 CV202 CV235 CV239 CV240 CV246 CV247 CV250 CV253 CV257 CV258 CV263 CV266 CV267 CV273 CV274 CV277 CV282 CV283 CV286 PC1030 PC1033 PC1034 PC1036-PC1050 PC1052 PC1053 PC1055 PC1056 PC1083-PC1090 PC1092-PC1099 PC1125 PC1126 PC1147-PC1153 PC1164 = C_0201
CC40 = C_0603: room: CPU
CD1-CD9 CD17 CD18 CD21-CD37 CD47-CD55 = C_0402: room: MEMORY
CD10-CD15 CD19 CD20 CD38-CD45 = C_0603: room: MEMORY
CD16 CD46 = C_D3: room: MEMORY
CE20 CE23 CE24 = C_0402: room: KBC
CE22 CE25 = C_0603: room: KBC
CI1 CI8 = C_MP6VLPS220MC4R2: room: USB
CI3 CI4 CI7 CI10 CI11 CI13 CI14 = C_0402: room: USB
CI6 CI12 = C_0805: room: USB
CL15 = C_0402: room: LAN
CL19 CV23 CV26 CV27 = C_0402: room: HDMI
CL33 = C_1206
CLRP1-CLRP3 = SHORTPADS: User Part Number: PART#
CV2-CV8 = C_0603: room: EDP
CV52 = C_0402: room: CRT
CV60 CV66 CV70 CV71 = C_0402: room: DP12412
CV72-CV75 CV77 CV78 CV80 = C_0201: room: DP12412
CV81 = C_0201: room: TOUCH
CV82 = C_0201: room: DP2320
CV83 CV105 CV106 = C_0402: room: DP2320
DA8 DC1 DX5 DX6 = BAT54C-7-F_SOT23-3
DA10 DA13 DA14 = AZ5125-02SPR7G_SOT23-3
DA12 = AZ5123-02SPR7G_SOT23-3
DB1 JDEG1 = ACES_51522-01001-001_10P
DC2-DC7 DV1 = RB751S40T1G_SOD523-2
DC8 DE4 DM1 DX3 DX7-DX9 = RB551V-30_SOD323-2
DE2 = L03ESDL5V0CC3-2_SOT23-3
DE3 = AZ5125-01HPR7G_SOD523-2
DI1 DI4 = IP4292CZ10-TBR_XSON10_2P5X1: room: USB
DI2 DI5 = L30ESDL5V0C3-2_SOT23-3: room: USB
DI3 = IP4292CZ10-TBR_XSON10_2P5X1
DX2 = PESD5V0U2BT_SOT23-3
DX4 = BAW56W_SOT323-3
FD1-FD4 = FIDUCIAL_C40M80: room: LED
FE1 = F_NANOSMDC050F-13P2-2
FX1 = F_1206L150PR
FX2 FX3 = F_SMD1812P110TF-24
H1 H20 = H_2P8N: room: LED
H2-H7 H11 H12 = H_2P8: room: LED
H8 = H_2P8-G: room: LED
H9 = H_2P8
H13-H16 = H_3P6-G: room: LED
H17 H18 = H_3P3-G: room: LED
H19 = H_3P3: room: LED
H21 = H_2P8N
H22 = H_2P8X3P3N
H23 = H_2P8X4P8N
HE1 PH601-PH605 PR3 PR4 PR20 PR28 PR29 PR31-PR33 PR37 PR110 PR115 PR117 PR118 PR204 PR209 PR310 PR311 PR313-PR315 PR501 PR601 PR604 PR605 PR608 PR610-PR613 PR617 PR618 PR621-PR623 PR626 PR628-PR633 PR635-PR652 PR654-PR658 PR678 PR682 PR727 PR729 PR731 PR732 PR737-PR742 PR744-PR746 PR749-PR755 PR757 PR760 PR762-PR764 PR801 PR802 PR804-PR810 PR813 PR814 PR818 PR824 PR825 R2448 R2452-R2460 RA10-RA14 RA19 RA53 RA55 RA56 RA79-RA84 RA130 RA165 RA166 RA1109 RA1112 RA1114 RC3 RC5 RC6 RC13 RC16 RC37 RC39 RC40 RC43-RC68 RC76 RC80 RC92-RC96 RC101 RC104 RC105 RC107 RC108 RC110 RC111 RC115 RC117 RC129 RC130 RC144 RC166 RC174 RC177 RC179-RC181 RC184 RC185 RC191-RC193 RC196 RC199-RC206 RC210 RC211 RC214-RC234 RC312 RC314-RC327 RC329 RC330 RC361 RC388-RC391 RC394-RC400 RC402 RD1 RD9 RD11 RD14-RD16 RD18-RD21 RE50 RE61 RE329 RE330 RE332-RE339 RE343 RE344 RE347-RE361 RE363-RE367 RE369-RE374 RE376 RE378-RE380 RE383 RE384 RE386-RE399 RE401-RE403 RI3-RI6 RI19-RI23 RI26 RI31 RI32 RI35 RI36 RI40 RI42 RI44 RI46 RI48-RI50 RI52-RI57 RI87-RI91 RI93 RI94 RI97-RI100 RI103-RI106 RL27 RL31 RL33 RL35 RL39 RL40 RM8 RM9 RM11 RM12 RM14 RS18-RS31 RS33-RS38 RV6 RV9 RV21 RV23 RV24 RV41-RV49 RV61-RV69 RV80 RV94-RV101 RV107 RV108 RV111-RV116 RV129 RV201-RV206 RV208 RV212 RV2437-RV2440 RV2447 RV2706 RV2717 RV2719 RV2720 RX9 RX10 RX12-RX17 RX24 RX26 RX31 RX33-RX49 RZ75 = R_0402
J510 J511 JP13-JP19 PJP105 PJP106 PJP206 PJP301 PJP501 PJP502 PJP801 = JUMP_43X79
J521 JP3 PJP603 = JUMP_43X39
JC1 = ACES_91960-0084N_8P
JCAM3D = STARC_111D10-000000-G4-R_10P
JDIMM1 = BELLW_80001-1021_204P: room: CPU
JDIMM2 = FOX_AS0A626-U4SN-7F_204P: room: CPU
JEDP = STARC_107K40-000001-G2_40P
JFAN = ACES_88231-03041_3P
JHDD = E-T_4260K-F10N-00L_10P
JHDMI = CONCR_099ATAC19NBLCNF_19P
JHP = SINGA_2SJ3080-001111F_6P
JIO = ACES_51524-0160N-001_16P
JKB = HB_A823020-SBHR21_30P
JKBBL = ACES_50524-00401-P01_4P-T
JLAN = SDAN_601028-008041_8P-T
JLED JTP = ACES_51524-0080N-001_8P
JNGFF = LOTES_APCI0019-P009A_67P
JRTC = ACES_50271-0020N-001_2P
JSPK = ACES_50278-00401-001_4P
JUSB1 JUSB2 = TAITW_PUBAU6-09FLBS1NN4H0_9P: room: USB
JWDB1 = CVILU_CI1804M1VRA-NH_4P
LA1 = MURAT_BLM15PX221SN1D_2P
LA3 = MURAT_BLM15BD601SN1D_2P: room: AJACK
LA4 LA10 = MURAT_BLM15BD601SN1D_2P
LA5-LA9 = MURAT_BLM15BD601SN1D_2P: room: CODEC
LI2 LI5 = INPAQ_MCM1012B900F06BP_4P: room: USB
LI8 LI11 LX6 = INPAQ_MCM1012B900F06BP_4P
LI9 LI10 = MURAT_DLW21SN670HQ2L_4P
LL1 = MURAT_LQM2MPN2R2NG0L_2P
LV3 = MURAT_BLM18PG331SN1D_2P: room: HDMI
LV4 LV5 = TDK_MPZ1608S300AT_2P
LX1 RA1110 RA1111 RI111 RV209 = R0805_0OHM
PBATT = ALLTO_C144LS-109A9-L_9P-T
PC1 PC3 PC4 = C_0402: room: P_DCIN
PC100 PC201 PC203 PC301 PC303 PC307 = C_0402: room: ETY-ROOM
PC102 PC111 PC114 PC200 PC204 PC209 PC302 PC304 = C_0603: room: ETY-ROOM
PC105 PC109 PC110 PC205 PC211 PC212 PC305 PC306 PC308-PC310 = C_0805: room: ETY-ROOM
PC113 PC115 = C_0402: room: 3V5V
PC208 = C_0402: room: ADP3209
PC213 = C_0402: room: CPU_CORE
PC606 = C_VSS330M1ETR-0604
PC705 PC708 PC711 = C_0402: room: CHARGER
PC721 = C_0603: room: ADP3209
PC816 PC817 = C_X
PC1062 PC1063 PC1127 = C_D2
PD2 = TVNST52302AB0_SOT523-3: room: ETY-ROOM
PD3 PD101 = TVNST52302AB0_SOT523-3
PD102 PD704-PD706 = SDMK0340L-7-F_SOD323-2
PJP1-PJP3 = JUMP_43X79-NPM
PJP102 = JUMP_43X118: room: ETY-ROOM
PJP103 PJP202 PJP302 PJP601 PJP602 PJP701 = JUMP_43X118
PJP200 = JUMP_43X118: room: DDR_VTT_0.75V
PJP203 = JUMP_43X79: room: ETY-ROOM
PJPDC = ACES_50299-00501-003_5P
PL1 PL3 PL4 = MURAT_BLM41PG600SN1L_2P: room: P_DCIN
PL2 = MURAT_BLM15AG102SN1D_2P: room: P_DCIN
PL100 PL101 PL200 = L_7X7X3_M_2P: room: ETY-ROOM
PL102 PL103 = TAIYO_FBMJ4516HS720NT_2P-NPM
PL301 = L_5X5X3_M_2P: room: ETY-ROOM
PL501 = CYNTE_PHT25201B-1R0MS_2P: room: CPU_CORE
PL601 = L_5X5X3_M_2P
PL602 = KC_FBMA-L11-4532158_2P-NPM
PL603 PL605 PL700 PL802 PL803 = L_7X7X3_M_2P
PL704 = L_5X5X3_M_2P-NPM
PL801 = TAI-T_HCB2012KF-121T50_2P-NPM
PQ1-PQ3 = 2N7002DW-T-R7_SOT363-6: room: P_DCIN
PQ5 = RHU002N06_SOT323-3
PQ6 = FDV301N_NL_SOT23-3: room: ETY-ROOM
PQ201 PQ501 = AON7934_DFN3X3A8-10
PQ704 PQ708 PQ740 = SIS412DN-T1-GE3_POWERPAK8-5
PQ707 PQ709 = 2N7002DW-T-R7_SOT363-6
PQ710 = LMUN5113T1G_SOT323-3
PQ711 = LTC015EUBFS8TL_UMT3F
PQ717 PQ718 = SIR472DP-T1-GE3_POWERPAK8-5
PQ800 PQ801 = AON6992_DFN5X6D-8-7
PR2 PR6-PR10 PR15 PR16 PR18 = R_0402: room: P_DCIN
PR5 PR627 PR663 PR676 PR743 PR766 PR821 PR822 = R_1206
PR100 PR111 = R0603_0OHM: room: ETY-ROOM
PR102 PR103 PR107 PR108 PR113 PR114 PR205 PR207 PR208 PR302 PR307 = R_0402: room: ETY-ROOM
PR106 PR112 PR203 PR303 = R_1206: room: ETY-ROOM
PR109 = R_0402: room: CPU_CORE
PR116 PR120 PR121 PR312 PR507 PR602 PR603 PR606 PR607 PR609 PR616 PR620 PR625 PR659 PR662 PR664 PR671 PR673 PR675 PR679 PR683 PR769 PR770 PR772 PR774-PR777 PR779 PR803 PR811 PR812 PR817 PR823 R2313 R2318 RA1113 RA1115 RC12 RC109 RC140 RC143 RC154 RC161 RC162 RC167 RC171 RC172 RC178 RC182 RC183 RC188 RC194 RC195 RC197 RC345 RC392 RD8 RD17 RE346 RE362 RE368 RE375 RE377 RE381 RE382 RE400 RM5 RM6 RM13 RS8 RV5 RV40 RV210 RV211 RX23 RX25 RX32 = R0402_0OHM
PR200 = R0603_0OHM: room: CPU_CORE
PR201 PR202 = R0402_0OHM: room: ETY-ROOM
PR206 = R_0603: room: ETY-ROOM
PR210 PR502 PR624 PR661 PR674 PR780 RV2718 RV2721 RX28-RX30 = R_0603
PR304 PR619 PR660 PR672 PR771 PR773 PR816 PR819 RC148 RC152 RC169 RC190 RC208 RC209 RC393 RE342 RE345 RE385 RL6 RM7 RM10 RV207 RX27 = R0603_0OHM
PR306 PR308 = R_0402: room: 1P5V
PR504-PR506 = R_0402: room: GPU_CORE
PR703 PR765 = R_1206_4P
PR720 = R_1206: room: CHARGER
PU100 = SY8286BRAC_QFN20_3X3: room: ETY-ROOM
PU102 = SY8286CRAC_QFN20_3X3
PU200 = RT8207PGQW_WQFN20_3X3: room: ETY-ROOM
PU301 = SYX196DQNC_QFN10_3X3
PU501 = SY8032ABC_SOT23-6: room: ETY-ROOM
PU602 = ISL62883CHRTZ-T_TQFN40_5X5
PU603 PU605 = AOZ5019QI_QFN23_5X3P5
PU606 = ISL95808HRZ-TS2378_DFN8_2X2
PU703 = ISL95812HRZ-T_QFN32_4X4
PU801 = RT8207MZQW_WQFN20_3X3
Q2407 Q2408 = MMST3904-7-F_SOT323-3
Q2409 QC2 QC3 QE6 QI1 QI2 QX4 RI1 = DMN66D0LDW-7_SOT363-6
QC1 = 2N7002K_SOT23-3: room: CPU
QC4 QE10 QV74 QX3 = 2N7002K_SOT23-3
QE5 = SI3456BDV-T1-E3_TSOP6: room: THERMAL
QE7 QE8 QV4 = 2N7002BKW_SOT323-3
QE9 = NTK3139PT1G_SOT723-3
QE11 = LN2306LT1G_SOT23-3
QV2 QV5 QV8 = DMN65D8LDW-7_SOT363-6
QV3 = 2N7002E_SOT23-3
QV6 = 2N7002_SOT23-3
QV7 = AON6552_DFN5X6-8-5
QX5 = MMBT3904_NL_SOT23-3
RA4 = R_0402: room: CODEC
RA8 RA29-RA32 = R0402_0OHM: room: CODEC
RC1 RC2 RC4 RC7-RC11 RC14 RC15 RC17 RC21 RC78 RC89 RC91 RC98 RC99 RC102 RC103 RC106 RC112 RC113 RC116 RC118-RC127 = R_0402: room: CPU
RC31 = R_0402: room: FLASH ROM
RC35 RC38 = R_0402: room: SPI
RC128 RC141 RC163 = R0402_0OHM: room: CPU
RD10 RD12 RD13 = R_0402: room: MEMORY
RE58 = R_0402: room: KBC
RI95 RI96 RI101 RI102 RI107-RI110 RX21 RX22 = R_0402-NPM
RL1 = MURAT_BLM18AG601SN1D_L0603_2P
RL19 RL20 = R_0603: room: LOM
RP58 RP59 RPC1 RPC5 RPC7 RPC9-RPC11 RPC14 RPC18 RPE1-RPE6 RPV3 RPV5-RPV18 = RP_0804_8P4R
RV4 = R_0402: room: EDP
RV12 = R0402_0OHM: room: HDMI
RV20 = R_0402: room: HDMI
RV50-RV52 = R_0402: room: DP12412
RV58 = R0402_0OHM: room: DP12412
RV74 RV75 RV81-RV84 RV88 = R_0402: room: DP2320
RX4 = R_0805
SW1 = SW_SMT1-05-A_4P: room: CPU
T10 T11 T14-T19 T22 T23 T87-T91 T93 T121 T123-T125 T130-T133 T137 T139 T155-T159 T162 T163 T199 T213-T216 T219 T221 T223 T225 T230-T232 T242 T243 T2401 T4928 T4931-T4951 T4956 T4962-T4964 = TPC12
TL2 = LANKO_LF-H1201P-2_16P
U2301 UC5 UV10 = TPS22966DPUR_SON14_2X3
U2407 = EMC1403-2-AIZL-TR_MSOP10
U2409 = AOZ1336_DFN8_2X2
UA1 = ALC3234-CG_MQFN48_6X6: room: CODEC
UC1 = SKL-U_BGA_1356P-T: room: CPU
UC2 = W25R128FVSIQ_SO8
UC3 = TC7SH08FUF_SSOP5: room: SPI
UC4 UC6 = TPS22961DNYR_WSON8
UC7 UC12 UC13 = 74AUP1G07GW_TSSOP5
UC8 UL3 UX4 = SY6288C20AAC_SOT23-5
UC11 UV12 UV13 = TC7SH08FUF_SSOP5
UC15 = TC7SH08FU_SSOP5
UE3 = G993P1UF_SOP8
UE5 = MEC1404-NU-TR_VTQFP128_14X14
UE6 = SN74LVC1G06DCKR_SC70-5
UI5-UI7 = SY6288D20AAC_SOT23-5
UI8 = SN65LVPE502CPRGER_VQFN24_4X4
UL1 = RTL8106EUS-CG_QFN32_4X4: room: LAN
US2 = PS8520BTQFN20GTR2_TQFN20_4X4
UV1 = N16S-GT-S-A2_BGA_595P: room: EDP
UV4-UV6 UV9 UV14 UV15 = MT41K256M16HA-125M-E_FBGA_96P
UV7 UV8 = MT41K256M16HA-125M-E_FBGA_96P: room: DP125
UV23 = NC7ST32P5X_SC70-5
Y1 = Y_Q13FC135000040_2P
YC1 = Y_7V24000020_4P: room: CPU
YC2 = Y_9H03200031_2P: room: CPU
YL2 = Y_FSX3M-25PM20FDO_4P
YV1 = Y_7V27000050_4P

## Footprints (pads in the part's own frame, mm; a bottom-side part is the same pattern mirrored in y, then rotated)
2N7002_SOT23-3
  oval 1.016x1.524 smd: 1(0,0) 2(0.965,2.083) 3(-0.965,2.083)
2N7002BKW_SOT323-3
  oval 0.61x0.559 smd: 1(0,0) 2(-0.65,-1.85) 3(0.65,-1.85)
2N7002DW-T-R7_SOT363-6
  oval 0.381x1.397 smd: 1(0,0) 2(0.65,0) 3(1.3,0) 4(1.3,1.725) 5(0.65,1.725) 6(0,1.725)
2N7002E_SOT23-3
  oval 1.016x1.524 smd: 1(0,0) 2(0.965,2.083) 3(-0.965,2.083)
2N7002K_SOT23-3
  oval 1.016x1.524 smd: 1(0,0) 2(0.965,2.083) 3(-0.965,2.083)
74AUP1G07GW_TSSOP5
  oval 0.381x1.346 smd: 1(0,0) 2(0.65,0) 3(1.3,0) 4(1.3,1.79) 5(0,1.79)
ACES_50271-0020N-001_2P
  oval 0.787x1.6 smd: 1(0,0) 2(1.25,0)
  rect 2.108x2.997 smd: 3(3.8,-2.9) 4(-2.55,-2.9)
ACES_50278-00401-001_4P
  oval 0.787x1.905 smd: 1(0,0) 2(1.25,0) 3(2.5,0) 4(3.75,0)
  rect 1.295x3.353 smd: 5(-2.85,-4.925) 6(6.6,-4.925)
ACES_50299-00501-003_5P
  round 1.803 hole 1.803 unplated: (-0.2,5.2) (8.2,5.2)
  oval 0.889x2.388 smd: 1(0,0) 2(2,0) 3(4,0) 4(6,0) 5(8,0)
ACES_50524-00401-P01_4P-T
  oval 0.305x1.295 smd: 1(0,0) 2(1,0) 3(2,0) 4(3,0)
  rect 1.803x2.21 smd: 5(-2.65,-5.65) 6(5.65,-5.65)
ACES_51522-01001-001_10P
  oval 0.305x1.295 smd: 1(0,0) 2(0.5,0) 3(1,0) 4(1.5,0) 5(2,0) 6(2.5,0) 7(3,0) 8(3.5,0) 9(4,0) 10(4.5,0)
  rect 2.489x1.905 smd: 11(-2.15,-3.3) 12(6.65,-3.3)
ACES_51524-0080N-001_8P
  oval 0.61x1.295 smd: 1(0,0) 2(1,0) 3(2,0) 4(3,0) 5(4,0) 6(5,0) 7(6,0) 8(7,0)
  rect 2.489x2.21 smd: 9(10,-3.05) 10(-3,-3.05)
ACES_51524-0160N-001_16P
  oval 0.61x1.295 smd: 1(0,0) 2(1,0) 3(2,0) 4(3,0) 5(4,0) 6(5,0) 7(6,0) 8(7,0) 9(8,0) 10(9,0) 11(10,0) 12(11,0) 13(12,0) 14(13,0) 15(14,0) 16(15,0)
  rect 2.159x2.21 smd: 17(-2.825,-3.05) 18(17.825,-3.05)
ACES_88231-03041_3P
  oval 0.787x1.905 smd: 1(0,0) 2(1.25,0) 3(2.5,0)
  rect 1.295x3.353 smd: 4(-2.85,-4.925) 5(5.35,-4.925)
ACES_91960-0084N_8P
  oval 0.889x1.346 smd: 1(0,0) 2(-1.27,0) 3(-2.54,0) 4(-3.81,0) 5(-3.81,-7.35) 6(-2.54,-7.35) 7(-1.27,-7.35) 8(0,-7.35)
ALC3234-CG_MQFN48_6X6
  oval 0.203x0.889 smd: 1(0,0) 2(0.4,0) 3(0.8,0) 4(1.2,0) 5(1.6,0) 6(2,0) 7(2.4,0) 8(2.8,0) 9(3.2,0) 10(3.6,0) 11(4,0) 12(4.4,0) 25(4.4,6.1) 26(4,6.1) 27(3.6,6.1) 28(3.2,6.1) 29(2.8,6.1) 30(2.4,6.1) 31(2,6.1) 32(1.6,6.1) 33(1.2,6.1) 34(0.8,6.1) 35(0.4,6.1) 36(0,6.1)
  oval 0.889x0.203 smd: 13(5.25,0.85) 14(5.25,1.25) 15(5.25,1.65) 16(5.25,2.05) 17(5.25,2.45) 18(5.25,2.85) 19(5.25,3.25) 20(5.25,3.65) 21(5.25,4.05) 22(5.25,4.45) 23(5.25,4.85) 24(5.25,5.25) 37(-0.85,5.25) 38(-0.85,4.85) 39(-0.85,4.45) 40(-0.85,4.05) 41(-0.85,3.65) 42(-0.85,3.25) 43(-0.85,2.85) 44(-0.85,2.45) 45(-0.85,2.05) 46(-0.85,1.65) 47(-0.85,1.25) 48(-0.85,0.85)
  rect 4.394x4.394 smd: 49(2.2,3.05)
ALLTO_C144LS-109A9-L_9P-T
  round 1.803 hole 1.194: 1(0,0) 2(2,0) 3(4,0) 4(6,0) 5(8,0) 6(10,0) 7(12,0) 8(14,0) 9(16,0)
  oval 1.6x3.404 hole 0.991x2.794: 10(19.125,0.25) 11(-3.125,0.25)
AON6552_DFN5X6-8-5
  oval 0.61x1.27 smd: 1(0,0) 2(1.27,0) 3(2.54,0) 4(3.81,0)
  custom 1.105x1.105 smd: 5(1.905,3.715)
AON6992_DFN5X6D-8-7
  oval 0.66x0.635 smd: 1(0,0) 3(3.81,5.67) 4(2.54,5.67) 5(1.27,5.67) 6(0,5.67)
  custom 0.485x0.485 smd: 2(1.905,0.655)
  rect 3.988x2.667 smd: 7(1.905,3.62)
AON7934_DFN3X3A8-10
  oval 0.457x0.508 smd: 1(0,0) 2(0.65,0) 3(1.3,0) 4(1.95,0) 5(1.95,2.76) 6(1.3,2.76) 7(0.65,2.76) 8(0,2.76)
  rect 2.54x1.041 smd: 9(0.975,1.813)
  rect 2.54x0.559 smd: 10(0.975,0.708)
AOZ1336_DFN8_2X2
  oval 0.254x0.787 smd: 1(0,0) 2(0.5,0) 3(1,0) 4(1.5,0) 5(1.5,2.2) 6(1,2.2) 7(0.5,2.2) 8(0,2.2)
  rect 1.499x0.889 smd: 9(0.75,1.1)
AOZ5019QI_QFN23_5X3P5
  oval 0.254x0.559 smd: 1(0,0) 2(0.5,0) 3(1,0) 4(1.5,0) 5(2,0)
  rect 2.972x1.524 smd: 6(1.375,1.235)
  custom 0.588x0.588 smd: 7(1.005,2.325)
  rect 1.956x0.686 smd: 8(1.255,4.587)
  oval 0.559x0.254 smd: 9(-0.57,2.825) 10(-0.57,1.825) 11(-0.57,1.325) 12(-0.57,0.825) 13(-0.57,0.325)
AZ5123-02SPR7G_SOT23-3
  oval 1.016x1.524 smd: 1(0,0) 2(0.965,2.083) 3(-0.965,2.083)
AZ5125-01HPR7G_SOD523-2
  rect 0.61x0.787 smd: 1(0,0) 2(1.5,0)
AZ5125-02SPR7G_SOT23-3
  oval 1.016x1.524 smd: 1(0,0) 2(0.965,2.083) 3(-0.965,2.083)
BAT54C-7-F_SOT23-3
  oval 1.016x1.524 smd: 1(0,0) 2(0.965,2.083) 3(-0.965,2.083)
BAW56W_SOT323-3
  oval 0.813x0.914 smd: 1(0,0) 2(0.65,1.6) 3(-0.65,1.6)
BELLW_80001-1021_204P
  round 1.092 hole 1.092 unplated: (-65.05,-4.1)
  round 1.6 hole 1.6 unplated: (1.75,-4.1)
  oval 0.356x2.007 smd: 1(0,0) 2(-0.3,-8.2) 3(-0.6,0) 4(-0.9,-8.2) 5(-1.2,0) 6(-1.5,-8.2) 7(-1.8,0) 8(-2.1,-8.2) 9(-2.4,0) 10(-2.7,-8.2) 11(-3,0) 12(-3.3,-8.2) 13(-3.6,0) 14(-3.9,-8.2) 15(-4.2,0) 16(-4.5,-8.2) 17(-4.8,0) 18(-5.1,-8.2) 19(-5.4,0) 20(-5.7,-8.2) 21(-6,0) 22(-6.3,-8.2) 23(-6.6,0) 24(-6.9,-8.2) 25(-7.2,0) 26(-7.5,-8.2) 27(-7.8,0) 28(-8.1,-8.2) 29(-8.4,0) 30(-8.7,-8.2) 31(-9,0) 32(-9.3,-8.2) 33(-9.6,0) 34(-9.9,-8.2) 35(-10.2,0) 36(-10.5,-8.2) 37(-10.8,0) 38(-11.1,-8.2) 39(-11.4,0) 40(-11.7,-8.2) 41(-12,0) 42(-12.3,-8.2) 43(-12.6,0) 44(-12.9,-8.2) 45(-13.2,0) 46(-13.5,-8.2) 47(-13.8,0) 48(-14.1,-8.2) 49(-14.4,0) 50(-14.7,-8.2) 51(-15,0) 52(-15.3,-8.2) 53(-15.6,0) 54(-15.9,-8.2) 55(-16.2,0) 56(-16.5,-8.2) 57(-16.8,0) 58(-17.1,-8.2) 59(-17.4,0) 60(-17.7,-8.2) 61(-18,0) 62(-18.3,-8.2) 63(-18.6,0) 64(-18.9,-8.2) 65(-19.2,0) 66(-19.5,-8.2) 67(-19.8,0) 68(-20.1,-8.2) 69(-20.4,0) 70(-20.7,-8.2) 71(-21,0) 72(-21.3,-8.2) 73(-24,0) 74(-24.3,-8.2) 75(-24.6,0) 76(-24.9,-8.2) 77(-25.2,0) 78(-25.5,-8.2) 79(-25.8,0) 80(-26.1,-8.2) 81(-26.4,0) 82(-26.7,-8.2) 83(-27,0) 84(-27.3,-8.2) 85(-27.6,0) 86(-27.9,-8.2) 87(-28.2,0) 88(-28.5,-8.2) 89(-28.8,0) 90(-29.1,-8.2) 91(-29.4,0) 92(-29.7,-8.2) 93(-30,0) 94(-30.3,-8.2) 95(-30.6,0) 96(-30.9,-8.2) 97(-31.2,0) 98(-31.5,-8.2) 99(-31.8,0) 100(-32.1,-8.2) 101(-32.4,0) 102(-32.7,-8.2) 103(-33,0) 104(-33.3,-8.2) 105(-33.6,0) 106(-33.9,-8.2) 107(-34.2,0) 108(-34.5,-8.2) 109(-34.8,0) 110(-35.1,-8.2) 111(-35.4,0) 112(-35.7,-8.2) 113(-36,0) 114(-36.3,-8.2) 115(-36.6,0) 116(-36.9,-8.2) 117(-37.2,0) 118(-37.5,-8.2) 119(-37.8,0) 120(-38.1,-8.2) 121(-38.4,0) 122(-38.7,-8.2) 123(-39,0) 124(-39.3,-8.2) 125(-39.6,0) 126(-39.9,-8.2) 127(-40.2,0) 128(-40.5,-8.2) 129(-40.8,0) 130(-41.1,-8.2) 131(-41.4,0) 132(-41.7,-8.2) 133(-42,0) 134(-42.3,-8.2) 135(-42.6,0) 136(-42.9,-8.2) 137(-43.2,0) 138(-43.5,-8.2) 139(-43.8,0) 140(-44.1,-8.2) 141(-44.4,0) 142(-44.7,-8.2) 143(-45,0) 144(-45.3,-8.2) 145(-45.6,0) 146(-45.9,-8.2) 147(-46.2,0) 148(-46.5,-8.2) 149(-46.8,0) 150(-47.1,-8.2) 151(-47.4,0) 152(-47.7,-8.2) 153(-48,0) 154(-48.3,-8.2) 155(-48.6,0) 156(-48.9,-8.2) 157(-49.2,0) 158(-49.5,-8.2) 159(-49.8,0) 160(-50.1,-8.2) 161(-50.4,0) 162(-50.7,-8.2) 163(-51,0) 164(-51.3,-8.2) 165(-51.6,0) 166(-51.9,-8.2) 167(-52.2,0) 168(-52.5,-8.2) 169(-52.8,0) 170(-53.1,-8.2) 171(-53.4,0) 172(-53.7,-8.2) 173(-54,0) 174(-54.3,-8.2) 175(-54.6,0) 176(-54.9,-8.2) 177(-55.2,0) 178(-55.5,-8.2) 179(-55.8,0) 180(-56.1,-8.2) 181(-56.4,0) 182(-56.7,-8.2) 183(-57,0) 184(-57.3,-8.2) 185(-57.6,0) 186(-57.9,-8.2) 187(-58.2,0) 188(-58.5,-8.2) 189(-58.8,0) 190(-59.1,-8.2) 191(-59.4,0) 192(-59.7,-8.2) 193(-60,0) 194(-60.3,-8.2) 195(-60.6,0) 196(-60.9,-8.2) 197(-61.2,0) 198(-61.5,-8.2) 199(-61.8,0) 200(-62.1,-8.2) 201(-62.4,0) 202(-62.7,-8.2) 203(-63,0) 204(-63.3,-8.2)
  rect 3.505x4.597 smd: 205(1.15,7.9) 206(-64.45,7.9)
C_0201
  rect 0.381x0.356 smd: 1(0,0) 2(0.584,0)
C_0402
  rect 0.508x0.559 smd: 1(0,0) 2(0.914,0)
C_0603
  rect 0.635x0.889 smd: 1(0,0) 2(1.397,0)
C_0805
  rect 0.813x1.397 smd: 1(0,0) 2(1.702,0)
C_1206
  rect 1.016x1.651 smd: 1(0,0) 2(2.667,0)
C_D2
  rect 2.388x2.794 smd: 1(0,0) 2(6.4,0)
C_D3
  rect 2.388x2.794 smd: 1(0,0) 2(6.4,0)
C_MP6VLPS220MC4R2
  oval 3.505x1.6 smd: 1(0,0) 2(-5.6,0)
C_VSS330M1ETR-0604
  oval 3.505x1.6 smd: 1(0,0) 2(-5.4,0)
C_X
  rect 1.803x2.896 smd: 1(0,0) 2(6,0)
CONCR_099ATAC19NBLCNF_19P
  round 0.813 hole 0.559: 1(0,0) 2(0.5,1.55) 3(1,0) 4(1.5,1.55) 5(2,0) 6(2.5,1.55) 7(3,0) 8(3.5,1.55) 9(4,0) 10(4.5,1.55) 11(5,0) 12(5.5,1.55) 13(6,0) 14(6.5,1.55) 15(7,0) 16(7.5,1.55) 17(8,0) 18(8.5,1.55) 19(9,0)
  oval 1.499x2.21 hole 0.889x1.6: 20(-2.75,1.7) 21(-4.65,-6.5) 22(11.75,1.7) 23(13.65,-7.75)
CVILU_CI1804M1VRA-NH_4P
  oval 0.508x0.991 smd: 1(0,-0.05) 2(-0.8,-0.05) 3(-1.6,-0.05) 4(-2.4,-0.05)
  rect 1.194x1.702 smd: 5(-3.7,1.4) 6(1.3,1.4)
CYNTE_PHT25201B-1R0MS_2P
  rect 0.889x2.108 smd: 1(0,0) 2(1.7,0)
DMN65D8LDW-7_SOT363-6
  oval 0.432x0.61 smd: 1(0,0) 2(0.65,0) 3(1.3,0) 4(1.3,1.9) 5(0.65,1.9) 6(0,1.9)
DMN66D0LDW-7_SOT363-6
  oval 0.432x0.61 smd: 1(0,0) 2(0.65,0) 3(1.3,0) 4(1.3,1.9) 5(0.65,1.9) 6(0,1.9)
E-T_4260K-F10N-00L_10P
  oval 0.508x0.991 smd: 1(0,0) 2(-0.8,0) 3(-1.6,0) 4(-2.4,0) 5(-3.2,0) 6(-4,0) 7(-4.8,0) 8(-5.6,0) 9(-6.4,0) 10(-7.2,0)
  rect 1.194x1.702 smd: 11(1.3,-1.95) 12(-8.5,-1.95)
EMC1403-2-AIZL-TR_MSOP10
  oval 0.254x1.626 smd: 1(0,0) 2(0.5,0) 3(1,0) 4(1.5,0) 5(2,0) 6(2,4.3) 7(1.5,4.3) 8(1,4.3) 9(0.5,4.3) 10(0,4.3)
F_1206L150PR
  rect 0.991x1.803 smd: 1(0,0) 2(2.8,0)
F_NANOSMDC050F-13P2-2
  rect 0.991x1.6 smd: 1(0,0) 2(3,0)
F_SMD1812P110TF-24
  rect 1.778x3.15 smd: 1(0,0) 2(5.23,0)
FDV301N_NL_SOT23-3
  oval 1.016x1.524 smd: 1(0,0) 2(0.965,2.083) 3(-0.965,2.083)
FIDUCIAL_C40M80
  round 1.016 smd: 1(0,0)
FOX_AS0A626-U4SN-7F_204P
  round 1.6 hole 1.6 unplated: (-1.75,4.1)
  round 1.092 hole 1.092 unplated: (65.05,4.1)
  oval 0.356x2.007 smd: 1(0,0) 2(0.3,8.2) 3(0.6,0) 4(0.9,8.2) 5(1.2,0) 6(1.5,8.2) 7(1.8,0) 8(2.1,8.2) 9(2.4,0) 10(2.7,8.2) 11(3,0) 12(3.3,8.2) 13(3.6,0) 14(3.9,8.2) 15(4.2,0) 16(4.5,8.2) 17(4.8,0) 18(5.1,8.2) 19(5.4,0) 20(5.7,8.2) 21(6,0) 22(6.3,8.2) 23(6.6,0) 24(6.9,8.2) 25(7.2,0) 26(7.5,8.2) 27(7.8,0) 28(8.1,8.2) 29(8.4,0) 30(8.7,8.2) 31(9,0) 32(9.3,8.2) 33(9.6,0) 34(9.9,8.2) 35(10.2,0) 36(10.5,8.2) 37(10.8,0) 38(11.1,8.2) 39(11.4,0) 40(11.7,8.2) 41(12,0) 42(12.3,8.2) 43(12.6,0) 44(12.9,8.2) 45(13.2,0) 46(13.5,8.2) 47(13.8,0) 48(14.1,8.2) 49(14.4,0) 50(14.7,8.2) 51(15,0) 52(15.3,8.2) 53(15.6,0) 54(15.9,8.2) 55(16.2,0) 56(16.5,8.2) 57(16.8,0) 58(17.1,8.2) 59(17.4,0) 60(17.7,8.2) 61(18,0) 62(18.3,8.2) 63(18.6,0) 64(18.9,8.2) 65(19.2,0) 66(19.5,8.2) 67(19.8,0) 68(20.1,8.2) 69(20.4,0) 70(20.7,8.2) 71(21,0) 72(21.3,8.2) 73(24,0) 74(24.3,8.2) 75(24.6,0) 76(24.9,8.2) 77(25.2,0) 78(25.5,8.2) 79(25.8,0) 80(26.1,8.2) 81(26.4,0) 82(26.7,8.2) 83(27,0) 84(27.3,8.2) 85(27.6,0) 86(27.9,8.2) 87(28.2,0) 88(28.5,8.2) 89(28.8,0) 90(29.1,8.2) 91(29.4,0) 92(29.7,8.2) 93(30,0) 94(30.3,8.2) 95(30.6,0) 96(30.9,8.2) 97(31.2,0) 98(31.5,8.2) 99(31.8,0) 100(32.1,8.2) 101(32.4,0) 102(32.7,8.2) 103(33,0) 104(33.3,8.2) 105(33.6,0) 106(33.9,8.2) 107(34.2,0) 108(34.5,8.2) 109(34.8,0) 110(35.1,8.2) 111(35.4,0) 112(35.7,8.2) 113(36,0) 114(36.3,8.2) 115(36.6,0) 116(36.9,8.2) 117(37.2,0) 118(37.5,8.2) 119(37.8,0) 120(38.1,8.2) 121(38.4,0) 122(38.7,8.2) 123(39,0) 124(39.3,8.2) 125(39.6,0) 126(39.9,8.2) 127(40.2,0) 128(40.5,8.2) 129(40.8,0) 130(41.1,8.2) 131(41.4,0) 132(41.7,8.2) 133(42,0) 134(42.3,8.2) 135(42.6,0) 136(42.9,8.2) 137(43.2,0) 138(43.5,8.2) 139(43.8,0) 140(44.1,8.2) 141(44.4,0) 142(44.7,8.2) 143(45,0) 144(45.3,8.2) 145(45.6,0) 146(45.9,8.2) 147(46.2,0) 148(46.5,8.2) 149(46.8,0) 150(47.1,8.2) 151(47.4,0) 152(47.7,8.2) 153(48,0) 154(48.3,8.2) 155(48.6,0) 156(48.9,8.2) 157(49.2,0) 158(49.5,8.2) 159(49.8,0) 160(50.1,8.2) 161(50.4,0) 162(50.7,8.2) 163(51,0) 164(51.3,8.2) 165(51.6,0) 166(51.9,8.2) 167(52.2,0) 168(52.5,8.2) 169(52.8,0) 170(53.1,8.2) 171(53.4,0) 172(53.7,8.2) 173(54,0) 174(54.3,8.2) 175(54.6,0) 176(54.9,8.2) 177(55.2,0) 178(55.5,8.2) 179(55.8,0) 180(56.1,8.2) 181(56.4,0) 182(56.7,8.2) 183(57,0) 184(57.3,8.2) 185(57.6,0) 186(57.9,8.2) 187(58.2,0) 188(58.5,8.2) 189(58.8,0) 190(59.1,8.2) 191(59.4,0) 192(59.7,8.2) 193(60,0) 194(60.3,8.2) 195(60.6,0) 196(60.9,8.2) 197(61.2,0) 198(61.5,8.2) 199(61.8,0) 200(62.1,8.2) 201(62.4,0) 202(62.7,8.2) 203(63,0) 204(63.3,8.2)
  rect 3.505x4.597 smd: 205(-1.15,16.1) 206(64.45,16.1)
G993P1UF_SOP8
  oval 0.635x1.854 smd: 1(0,0) 2(1.27,0) 3(2.54,0) 4(3.81,0) 5(3.81,5.165) 6(2.54,5.165) 7(1.27,5.165) 8(0,5.165)
H_2P8
  round 3.302 hole 2.794: 1(0,0)
H_2P8-G
  round 3.302 hole 2.794: 1(0,0)
H_2P8N
  round 2.794 hole 2.794 unplated: (0,0)
H_2P8X3P3N
  oval 2.794x3.302 hole 2.794x3.302 unplated: (0,0)
H_2P8X4P8N
  oval 2.794x4.801 hole 2.794x4.801 unplated: (0,0)
H_3P3
  round 3.81 hole 3.302: 1(0,0)
H_3P3-G
  round 3.81 hole 3.302: 1(0,0)
H_3P6-G
  round 4.115 hole 3.607: 1(0,0)
HB_A823020-SBHR21_30P
  oval 0.305x1.295 smd: 1(0,0) 2(0.8,0) 3(1.6,0) 4(2.4,0) 5(3.2,0) 6(4,0) 7(4.8,0) 8(5.6,0) 9(6.4,0) 10(7.2,0) 11(8,0) 12(8.8,0) 13(9.6,0) 14(10.4,0) 15(11.2,0) 16(12,0) 17(12.8,0) 18(13.6,0) 19(14.4,0) 20(15.2,0) 21(16,0) 22(16.8,0) 23(17.6,0) 24(18.4,0) 25(19.2,0) 26(20,0) 27(20.8,0) 28(21.6,0) 29(22.4,0) 30(23.2,0)
  rect 1.803x2.21 smd: 31(25.55,-5.65) 32(-2.35,-5.65)
INPAQ_MCM1012B900F06BP_4P
  rect 0.711x0.305 smd: 1(0,0) 2(1.25,0) 3(1.25,-0.5) 4(0,-0.5)
IP4292CZ10-TBR_XSON10_2P5X1
  oval 0.254x0.889 smd: 1(0,0)
  oval 0.254x0.838 smd: 2(0.5,-0.025) 3(1,-0.025) 4(1.5,-0.025) 5(2,-0.025) 6(2,1.125) 7(1.5,1.125) 8(1,1.125) 9(0.5,1.125) 10(0,1.125)
ISL62883CHRTZ-T_TQFN40_5X5
  oval 0.203x0.991 smd: 1(0,0) 2(0.4,0) 3(0.8,0) 4(1.2,0) 5(1.6,0) 6(2,0) 7(2.4,0) 8(2.8,0) 9(3.2,0) 10(3.6,0) 21(3.6,4.95) 22(3.2,4.95) 23(2.8,4.95) 24(2.4,4.95) 25(2,4.95) 26(1.6,4.95) 27(1.2,4.95) 28(0.8,4.95) 29(0.4,4.95) 30(0,4.95)
  oval 0.991x0.203 smd: 11(4.275,0.675) 12(4.275,1.075) 13(4.275,1.475) 14(4.275,1.875) 15(4.275,2.275) 16(4.275,2.675) 17(4.275,3.075) 18(4.275,3.475) 19(4.275,3.875) 20(4.275,4.275) 31(-0.675,4.275) 32(-0.675,3.875) 33(-0.675,3.475) 34(-0.675,3.075) 35(-0.675,2.675) 36(-0.675,2.275) 37(-0.675,1.875) 38(-0.675,1.475) 39(-0.675,1.075) 40(-0.675,0.675)
  rect 3.505x3.505 smd: 41(1.8,2.475)
ISL95808HRZ-TS2378_DFN8_2X2
  oval 0.254x0.787 smd: 1(0,0) 2(0.5,0) 3(1,0) 4(1.5,0) 5(1.5,2.2) 6(1,2.2) 7(0.5,2.2) 8(0,2.2)
  rect 1.549x0.889 smd: 9(0.75,1.1)
ISL95812HRZ-T_QFN32_4X4
  oval 0.203x0.914 smd: 1(0,0) 2(0.4,0) 3(0.8,0) 4(1.2,0) 5(1.6,0) 6(2,0) 7(2.4,0) 8(2.8,0) 17(2.8,4.077) 18(2.4,4.077) 19(2,4.077) 20(1.6,4.077) 21(1.2,4.077) 22(0.8,4.077) 23(0.4,4.077) 24(0,4.077)
  oval 0.914x0.203 smd: 9(3.438,0.639) 10(3.438,1.039) 11(3.438,1.438) 12(3.438,1.838) 13(3.438,2.239) 14(3.438,2.639) 15(3.438,3.039) 16(3.438,3.438) 25(-0.639,3.438) 26(-0.639,3.039) 27(-0.639,2.639) 28(-0.639,2.239) 29(-0.639,1.838) 30(-0.639,1.438) 31(-0.639,1.039) 32(-0.639,0.639)
  rect 2.642x2.642 smd: 33(1.4,2.039)
JUMP_43X39
  custom 0.191x0.191 smd: 1(0,0) 2(0.914,0)
JUMP_43X79
  custom 0.188x0.188 smd: 1(0,0) 2(1.1,0)
JUMP_43X79-NPM
  custom 0.188x0.188 smd: 1(0,0) 2(1.1,0)
JUMP_43X118
  custom 0.187x0.187 smd: 1(0,0) 2(1.1,0)
KC_FBMA-L11-4532158_2P-NPM
  rect 1.803x3.404 smd: 1(0,0) 2(3.8,0)
L03ESDL5V0CC3-2_SOT23-3
  oval 1.016x1.524 smd: 1(0,0) 2(0.965,2.083) 3(-0.965,2.083)
L30ESDL5V0C3-2_SOT23-3
  oval 1.016x1.524 smd: 1(0,0) 2(0.965,2.083) 3(-0.965,2.083)
L_5X5X3_M_2P
  rect 2.159x2.794 smd: 1(0,0) 2(4.35,0)
L_5X5X3_M_2P-NPM
  rect 2.159x2.794 smd: 1(0,0) 2(4.35,0)
L_7X7X3_M_2P
  rect 2.362x3.505 smd: 1(0,0) 2(6.05,0)
LANKO_LF-H1201P-2_16P
  oval 0.635x1.905 smd: 1(0,0) 2(1.27,0) 3(2.54,0) 4(3.81,0) 5(5.08,0) 6(6.35,0) 7(7.62,0) 8(8.89,0) 9(8.89,8.763) 10(7.62,8.763) 11(6.35,8.763) 12(5.08,8.763) 13(3.81,8.763) 14(2.54,8.763) 15(1.27,8.763) 16(0,8.763)
LMUN5113T1G_SOT323-3
  oval 0.711x0.889 smd: 1(0,0) 2(0.65,1.9) 3(-0.65,1.9)
LN2306LT1G_SOT23-3
  oval 1.016x1.524 smd: 1(0,0) 2(0.965,2.083) 3(-0.965,2.083)
LOTES_APCI0019-P009A_67P
  round 1.092 hole 1.092 unplated: (-0.75,-5.275)
  round 1.6 hole 1.6 unplated: (19.25,-5.275)
  oval 0.305x1.549 smd: 1(0,0) 2(0.25,-7.55) 3(0.5,0) 4(0.75,-7.55) 5(1,0) 6(1.25,-7.55) 7(1.5,0) 8(1.75,-7.55) 9(2,0) 10(2.25,-7.55) 11(2.5,0) 12(2.75,-7.55) 13(3,0) 14(3.25,-7.55) 15(3.5,0) 16(3.75,-7.55) 17(4,0) 18(4.25,-7.55) 19(4.5,0) 20(4.75,-7.55) 21(5,0) 22(5.25,-7.55) 23(5.5,0) 24(7.75,-7.55) 25(8,0) 26(8.25,-7.55) 27(8.5,0) 28(8.75,-7.55) 29(9,0) 30(9.25,-7.55) 31(9.5,0) 32(9.75,-7.55) 33(10,0) 34(10.25,-7.55) 35(10.5,0) 36(10.75,-7.55) 37(11,0) 38(11.25,-7.55) 39(11.5,0) 40(11.75,-7.55) 41(12,0) 42(12.25,-7.55) 43(12.5,0) 44(12.75,-7.55) 45(13,0) 46(13.25,-7.55) 47(13.5,0) 48(13.75,-7.55) 49(14,0) 50(14.25,-7.55) 51(14.5,0) 52(14.75,-7.55) 53(15,0) 54(15.25,-7.55) 55(15.5,0) 56(15.75,-7.55) 57(16,0) 58(16.25,-7.55) 59(16.5,0) 60(16.75,-7.55) 61(17,0) 62(17.25,-7.55) 63(17.5,0) 64(17.75,-7.55) 65(18,0) 66(18.25,-7.55) 67(18.5,0)
  rect 1.194x2.743 smd: 68(-1.1,-0.775) 69(19.6,-0.775)
